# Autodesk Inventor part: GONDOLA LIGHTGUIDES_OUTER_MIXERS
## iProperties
Shininess: 64.0
Length Units: 11272
Angle Units: 11279
Time Units: 11290
Mass Units: 11286
Length Display Precision: 3
Angle Display Precision: 2
Compacted: True
Part Number: GONDOLA LIGHTGUIDES_OUTER_MIXERS
Document SubType Name: Modeling
Created: 2004-08
Designer: John Blackburn
Manufacturer: Standard
Standards Organization: Custom
Material: Lexan, Clear
Density: 0.0
Volumn: 0.0
Area: 0.0
PropertySet Name: Model Information
Control State: 0
Master: False
Checked Out: False
Author: John Blackburn
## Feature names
1. Base1
